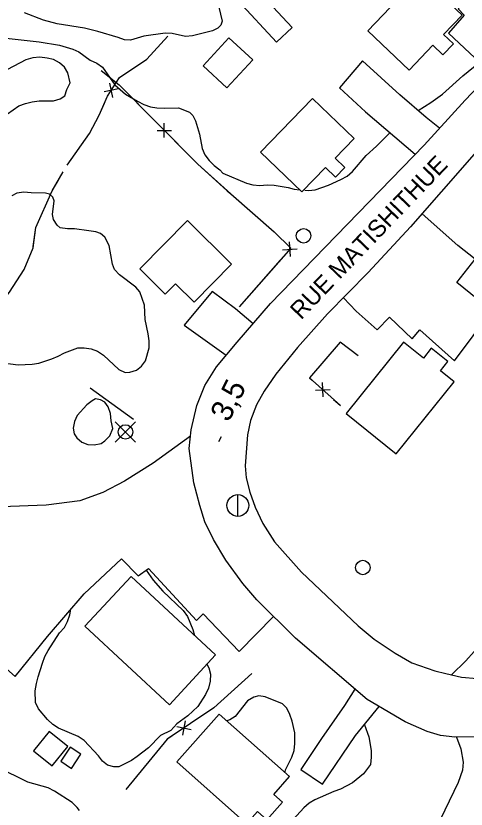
# Model space of a CAD drawing. Extents: x 282461 to 284471, y 5554090 to 5557646.
# Drawn here: x 282851.1 to 282913.1, y 5554638 to 5554747.1 of the extents above; entities that cross this region are included whole.
import ezdxf

# ---------------------------------------------------------------- set-up
doc = ezdxf.new("R2010")
doc.units = 0
for name, color, linetype in [('Niveau 1', 7, 'Continuous'), ('Niveau 15', 7, 'Continuous'), ('Niveau 19', 7, 'Continuous'), ('Niveau 2', 7, 'Continuous'), ('Niveau 21', 7, 'Continuous'), ('Niveau 3', 7, 'Continuous'), ('Niveau 31', 7, 'Continuous'), ('Niveau 36', 7, 'Continuous'), ('Niveau 37', 7, 'Continuous')]:
    doc.layers.add(name, color=color, linetype=linetype)

msp = doc.modelspace()

# ---------------------------------------------------------------- linework, layer by layer
at = {"layer": 'Niveau 1'}
msp.add_lwpolyline([(282879.04, 5554748.29), (282879.48, 5554746.39), (282879.32, 5554745.81), (282878.92, 5554745.4), (282878.17, 5554745.04), (282875.41, 5554744.36), (282874.43, 5554744.28), (282872.63, 5554744.66), (282871.65, 5554744.7), (282868.71, 5554744.31), (282866.86, 5554743.76), (282866.05, 5554743.8), (282865.18, 5554744.13), (282862.39, 5554744.96), (282860.54, 5554745.39), (282856.77, 5554746.02), (282854.91, 5554746.52), (282852.29, 5554747.51)], dxfattribs=at)
at = {"layer": 'Niveau 19'}
for points in [[(282924.29, 5554747.53), (282921.44, 5554750.01), (282917.21, 5554753.94), (282911.98, 5554748.06), (282912.8, 5554747.21), (282910.65, 5554744.74), (282916.5, 5554739.24)], [(282909.42, 5554731.66), (282907.58, 5554733.1), (282903.97, 5554736.23), (282898.8, 5554740.9), (282895.63, 5554737.2), (282899.21, 5554733.9), (282906.05, 5554728.06)], [(282896.18, 5554708.33), (282897.94, 5554706.48), (282900.82, 5554703.92), (282902.52, 5554705.63), (282905.64, 5554702.67), (282906.69, 5554703.89), (282911.48, 5554699.62), (282916.63, 5554706.54), (282911.82, 5554710.4), (282914.34, 5554713.63), (282911.94, 5554715.5), (282907.03, 5554719.86)], [(282883.75, 5554704.75), (282881.35, 5554706.79), (282878.11, 5554709.18), (282874.25, 5554704.54), (282880.04, 5554700.41)], [(282875.13, 5554689.3), (282869.99, 5554685.58), (282866.06, 5554683.08), (282863.08, 5554681.53), (282859.91, 5554680.38), (282855.29, 5554679.79), (282849.14, 5554679.58), (282846.25, 5554679.36), (282844.07, 5554678.4), (282841.34, 5554675.87), (282835.83, 5554669.47), (282842.76, 5554663.5), (282851, 5554656.21), (282855.44, 5554661.71), (282860.5, 5554667.58), (282865.62, 5554672.41), (282867.92, 5554670.07), (282869.35, 5554671.08), (282875.95, 5554663.94), (282876.9, 5554664.84), (282881.84, 5554659.64), (282886.57, 5554664.48)], [(282940.21, 5554676.32), (282938.2, 5554677.94), (282931.93, 5554682.59), (282927.42, 5554676.8), (282928.53, 5554675.9), (282924.96, 5554671.55), (282921.6, 5554668.25), (282919.51, 5554667.11), (282917.59, 5554664.47), (282915.33, 5554660.96), (282913.06, 5554658.38), (282911.05, 5554656.44)], [(282897.78, 5554654.47), (282896.35, 5554652.22), (282893.15, 5554647.7), (282890.33, 5554643.43), (282893.32, 5554641.39), (282897.87, 5554648.08), (282901.09, 5554652.08)], [(282911.75, 5554647.87), (282912.34, 5554646.26), (282912.66, 5554644.41), (282912.57, 5554643.31), (282911.96, 5554641.62), (282902.15, 5554621.29), (282906.75, 5554619.05), (282912.5, 5554631.46), (282916.11, 5554639.08), (282916.56, 5554639.79), (282922.87, 5554633.89), (282925.53, 5554637.57), (282921.56, 5554641.23), (282918.83, 5554644.09), (282922.48, 5554649.58)]]:
    msp.add_lwpolyline(points, dxfattribs=at)
at = {"layer": 'Niveau 2'}
for points in [[(282849.36, 5554744.1), (282854.29, 5554743.55), (282857.13, 5554743.07), (282858.93, 5554742.52), (282859.75, 5554742.13), (282861.33, 5554741), (282862.26, 5554740.61), (282863.02, 5554740.04), (282864.74, 5554737.63), (282865.44, 5554736.95), (282866.21, 5554736.33), (282867.84, 5554735.37)], [(282858.12, 5554736.99), (282858.57, 5554737.87), (282858.26, 5554739.25), (282857.78, 5554740.06), (282857.13, 5554740.63), (282856.26, 5554741.08), (282855.39, 5554741.3), (282854.4, 5554741.4), (282853.42, 5554741.32), (282852.49, 5554741.07), (282849.97, 5554739.7)], [(282906.48, 5554734.06), (282908.23, 5554735.2), (282909.83, 5554736.33), (282912.62, 5554738.86), (282914.11, 5554740.04), (282914.98, 5554740.67)], [(282849.96, 5554733.62), (282851.5, 5554734.74), (282852.42, 5554735.05), (282853.34, 5554735.29), (282854.33, 5554735.43), (282856.29, 5554735.4), (282857.22, 5554735.7), (282857.84, 5554736.12), (282858.12, 5554736.99)], [(282867.84, 5554735.37), (282868.72, 5554734.92), (282869.65, 5554734.59), (282870.52, 5554734.43), (282871.5, 5554734.38), (282873.47, 5554734.47), (282874.98, 5554733.86), (282875.45, 5554733.4), (282875.81, 5554732.66), (282876.36, 5554730.81), (282876.74, 5554728.85), (282877.11, 5554727.99), (282877.7, 5554727.19), (282878.4, 5554726.5), (282879.16, 5554725.94), (282879.58, 5554725.48), (282882.84, 5554724.09), (282883.71, 5554723.87), (282884.7, 5554723.77), (282885.68, 5554723.84), (282886.66, 5554723.8), (282888.58, 5554723.48), (282889.39, 5554723.26), (282890.17, 5554723.18)], [(282890.88, 5554723.11), (282891.36, 5554723.06), (282892.28, 5554723.19), (282894.13, 5554723.8), (282895.85, 5554724.58), (282896.71, 5554725.06), (282897.45, 5554725.71), (282899.32, 5554727.88), (282900.75, 5554729.18), (282902.58, 5554731.03)], [(282863.95, 5554715.5), (282863.35, 5554716.65), (282862.77, 5554717.17), (282862.13, 5554717.39), (282861.14, 5554717.54), (282859.17, 5554717.8), (282858.19, 5554717.79), (282857.2, 5554717.94), (282856.79, 5554718.29), (282856.26, 5554719.09), (282856.13, 5554719.78), (282856.39, 5554721.64), (282856.21, 5554722.16), (282855.74, 5554722.55), (282855.16, 5554722.72), (282853.19, 5554722.74), (282852.2, 5554722.84), (282851.22, 5554722.71), (282850.53, 5554722.35)], [(282845.71, 5554699.82), (282851.44, 5554699.1), (282853.35, 5554699.18), (282854.27, 5554699.32), (282856.06, 5554699.92), (282856.92, 5554700.28), (282857.78, 5554700.76), (282859.62, 5554701.43), (282860.49, 5554701.44), (282861.47, 5554701.28), (282862.34, 5554700.95), (282863.16, 5554700.44), (282865.28, 5554698.45), (282866.15, 5554698.06), (282866.79, 5554698.07), (282867.71, 5554698.37), (282868.39, 5554698.9), (282868.96, 5554699.66), (282869.45, 5554701.41), (282869.43, 5554702.39), (282869.3, 5554703.37), (282868.92, 5554705.34), (282868.83, 5554707.3), (282868.17, 5554709.15), (282867.63, 5554709.77), (282865.35, 5554711.47), (282864.7, 5554712.22), (282864.4, 5554712.96), (282863.95, 5554715.5)], [(282864.24, 5554691.37), (282864.11, 5554692.41), (282863.8, 5554693.33), (282863.33, 5554693.96), (282862.74, 5554694.3), (282862.05, 5554694.4), (282861.59, 5554694.16), (282860.85, 5554693.57), (282859.54, 5554692.1), (282859.15, 5554691.29), (282858.99, 5554690.36), (282859.12, 5554689.61), (282859.48, 5554689.04), (282860.18, 5554688.47), (282861, 5554688.13), (282861.87, 5554688.09), (282862.85, 5554688.28), (282863.36, 5554688.63), (282864.04, 5554689.34), (282864.43, 5554690.33), (282864.24, 5554691.37)], [(282869.02, 5554670.85), (282870.01, 5554669.45), (282871.31, 5554667.97), (282874.14, 5554665.29), (282874.73, 5554664.49), (282875.45, 5554662.7), (282875.7, 5554661.87)], [(282871.01, 5554648.09), (282869.36, 5554646.39), (282867.82, 5554645.21), (282867.01, 5554644.67), (282865.29, 5554643.78), (282864.6, 5554643.77), (282863.73, 5554644.04), (282863.02, 5554644.55), (282862.49, 5554645.3), (282860.49, 5554647.41), (282859.67, 5554647.97), (282856.98, 5554649.09), (282856.17, 5554649.6), (282855.46, 5554650.28), (282854.22, 5554651.77), (282853.8, 5554652.63), (282853.77, 5554654.25), (282853.93, 5554655.24), (282854.15, 5554656.17), (282854.75, 5554658.03), (282855.08, 5554658.97), (282855.53, 5554659.78), (282857.11, 5554662.24), (282857.79, 5554662.95), (282858.19, 5554663.76), (282858.52, 5554664.7), (282858.68, 5554665.47)], [(282877.4, 5554657.9), (282877.68, 5554657.41), (282877.87, 5554656.54), (282877.83, 5554655.56), (282877.61, 5554654.63), (282877.22, 5554653.75), (282876.15, 5554652.11), (282874.78, 5554650.82), (282873.24, 5554649.69), (282872.44, 5554648.81), (282871.01, 5554648.09)], [(282889.11, 5554650.08), (282888.8, 5554651), (282888.38, 5554651.87), (282887.79, 5554652.44), (282885.41, 5554653.44), (282884.54, 5554653.54), (282883.85, 5554653.36), (282882.99, 5554652.88), (282881.29, 5554650.71), (282880.54, 5554650.24), (282880.13, 5554650.14)], [(282888.15, 5554643.12), (282888.23, 5554643.36), (282889.07, 5554645.11), (282889.4, 5554646.04), (282889.5, 5554647.02), (282889.48, 5554648.47), (282889.11, 5554650.08)], [(282899.09, 5554649.58), (282899.67, 5554647.93), (282899.99, 5554646.03), (282900.01, 5554645.1)], [(282900.01, 5554645.1), (282899.91, 5554644.12), (282898.94, 5554642.83), (282897.46, 5554641.59), (282895.8, 5554640.7), (282894.88, 5554640.39), (282892.24, 5554639.25), (282891.49, 5554638.78), (282890.75, 5554638.13), (282888.76, 5554636.01)], [(282859.84, 5554637.78), (282859.54, 5554638.18), (282858.83, 5554638.87), (282856.43, 5554640.45), (282855.56, 5554640.9), (282852.77, 5554641.67), (282848.51, 5554643.74)]]:
    msp.add_lwpolyline(points, dxfattribs=at)
at = {"layer": 'Niveau 21'}
for points in [[(282878.3, 5554675.07), (282877.1, 5554677.48), (282876.42, 5554679.73), (282875.62, 5554682.84), (282874.96, 5554687.58), (282875.21, 5554690.13), (282876.02, 5554693.51), (282877.13, 5554696.24), (282878.71, 5554698.82), (282881.55, 5554702.22), (282886.15, 5554707.51), (282907.28, 5554729.33), (282912.94, 5554735.51), (282919.4, 5554742.27), (282923.97, 5554747.21), (282929.38, 5554752.63), (282934.38, 5554758.26), (282952.63, 5554779.99), (282962.67, 5554792.32), (282966.75, 5554797.77), (282970.24, 5554803.68), (282971.64, 5554808.46), (282972.65, 5554813.8), (282973.48, 5554823.09)], [(282918.39, 5554732.87), (282905.44, 5554718.07), (282899.59, 5554711.78), (282894.01, 5554706.13), (282889.86, 5554701.49), (282886.88, 5554697.79), (282885.3, 5554695.45), (282884.23, 5554693.58), (282883.4, 5554691.42), (282882.97, 5554689.45), (282882.66, 5554685.21), (282882.81, 5554683.53), (282883.3, 5554681.57), (282884.03, 5554679.49), (282885.11, 5554677.25), (282886.71, 5554674.73), (282890.4, 5554670.57), (282898.2, 5554663.17), (282900.42, 5554661.36), (282903.32, 5554659.44), (282905.6, 5554658.09), (282908.77, 5554656.99), (282910.29, 5554656.61), (282912.43, 5554656.12), (282914.58, 5554655.93)], [(282977.15, 5554709.01), (282965.42, 5554696.55), (282958.45, 5554688.63), (282945.11, 5554673.19), (282939.64, 5554666.16), (282933.59, 5554659.25), (282926.34, 5554651.73), (282922.75, 5554649.66), (282918.67, 5554648.38), (282915.9, 5554647.93), (282911.51, 5554647.87), (282909.54, 5554648.12), (282907.73, 5554648.67), (282904.67, 5554650), (282899.45, 5554653.04), (282889.58, 5554661.49), (282884.25, 5554666.78), (282882.33, 5554668.99), (282880.02, 5554672.2), (282878.3, 5554675.07)]]:
    msp.add_lwpolyline(points, dxfattribs=at)
at = {"layer": 'Niveau 3'}
msp.add_line((282879.06, 5554688.53), (282879.42, 5554689.25), dxfattribs=at)
at = {"layer": 'Niveau 31'}
for points in [[(282912.51, 5554747.2), (282906.81, 5554752.65), (282899.55, 5554745.06), (282905.23, 5554739.62), (282908.51, 5554743.05), (282909.87, 5554741.76), (282911.32, 5554743.27), (282909.98, 5554744.55), (282912.51, 5554747.2)], [(282889.13, 5554745.51), (282883.87, 5554751.17), (282881.71, 5554749.17), (282886.97, 5554743.5), (282889.13, 5554745.51)], [(282883.71, 5554741.03), (282880.43, 5554744.07), (282876.86, 5554740.23), (282880.14, 5554737.19), (282883.71, 5554741.03)], [(282891.91, 5554735.73), (282884.79, 5554728.34), (282890.47, 5554722.87), (282893.73, 5554726.26), (282895.12, 5554724.91), (282896.4, 5554726.24), (282895.07, 5554727.53), (282897.65, 5554730.21), (282891.91, 5554735.73)], [(282880.79, 5554712.94), (282874.74, 5554718.93), (282868.16, 5554712.28), (282871.65, 5554708.83), (282873.06, 5554710.25), (282875.63, 5554707.72), (282880.79, 5554712.94)], [(282896.56, 5554692.42), (282903.46, 5554686.86), (282911.42, 5554696.76), (282909.53, 5554698.28), (282910.56, 5554699.55), (282908.28, 5554701.39), (282907.19, 5554700.03), (282904.45, 5554702.23), (282896.56, 5554692.42)], [(282878.6, 5554659.2), (282866.96, 5554669.99), (282860.61, 5554663.14), (282872.25, 5554652.34), (282878.6, 5554659.2)], [(282888.78, 5554642.44), (282879.09, 5554651.04), (282873.25, 5554644.46), (282882.85, 5554635.93), (282884.38, 5554637.65), (282885.66, 5554636.51), (282887.8, 5554638.93), (282886.61, 5554639.99), (282888.78, 5554642.44)], [(282858.24, 5554646.57), (282855.69, 5554648.64), (282853.54, 5554646.01), (282856.08, 5554643.93), (282858.24, 5554646.57)], [(282860.06, 5554645.54), (282858.59, 5554646.51), (282857.29, 5554644.56), (282858.77, 5554643.58), (282860.06, 5554645.54)]]:
    msp.add_lwpolyline(points, dxfattribs=at)
at = {"layer": 'Niveau 36'}
for p, q in [((282867.59, 5554688.44), (282864.77, 5554691.26)), ((282864.77, 5554688.44), (282867.59, 5554691.26)), ((282881.65, 5554678.25), (282881.65, 5554681.25))]:
    msp.add_line(p, q, dxfattribs=at)
for centre, radius in [((282890.7, 5554716.84), 1), ((282866.19, 5554689.86), 1), ((282881.66, 5554679.75), 1.5), ((282898.86, 5554671.21), 1)]:
    msp.add_circle(centre, radius, dxfattribs=at)
at = {"layer": 'Niveau 37'}
for p, q in [((282865.21, 5554737.08), (282863.26, 5554736.65)), ((282864.45, 5554735.89), (282864.02, 5554737.84)), ((282871.53, 5554730.35), (282871.53, 5554732.35)), ((282870.53, 5554731.35), (282872.53, 5554731.35)), ((282887.8, 5554714.93), (282889.8, 5554715.06)), ((282888.73, 5554716), (282888.86, 5554714)), ((282893.41, 5554694.67), (282893.3, 5554696.67)), ((282892.35, 5554695.61), (282894.35, 5554695.72)), ((282874.42, 5554650.11), (282874.04, 5554648.15)), ((282873.25, 5554649.32), (282875.21, 5554648.94))]:
    msp.add_line(p, q, dxfattribs=at)
for points in [[(282858.14, 5554726.58), (282861.25, 5554730.92), (282862.57, 5554733.43), (282863.72, 5554736.06), (282865.36, 5554738.63), (282869.13, 5554741.13), (282872.01, 5554744.3)], [(282865.31, 5554738.55), (282865.36, 5554738.63), (282869.13, 5554741.13), (282872.01, 5554744.3)], [(282862.82, 5554739.58), (282865.32, 5554737.59), (282876.15, 5554726.71), (282880.67, 5554722.61), (282886.65, 5554717.39), (282888.94, 5554715.16), (282881.85, 5554707.07)], [(282862.82, 5554739.58), (282865.32, 5554737.59), (282870.12, 5554732.77)], [(282858.14, 5554726.58), (282861.25, 5554730.92), (282862.57, 5554733.43), (282863.3, 5554735.1)], [(282872.94, 5554729.93), (282876.15, 5554726.71), (282880.19, 5554723.05)], [(282830.2, 5554676.25), (282829.95, 5554680.47), (282830.24, 5554684.17), (282830.82, 5554687.63), (282831.54, 5554690.24), (282835.62, 5554695.22), (282838.02, 5554698.32), (282840.56, 5554700.56), (282843.04, 5554702.24), (282847.81, 5554706.08), (282850.22, 5554709.07), (282852.25, 5554712.23), (282853.47, 5554715.2), (282853.83, 5554717.98), (282856.1, 5554723.04), (282857.63, 5554725.65)], [(282853.49, 5554715.37), (282853.83, 5554717.98), (282856.1, 5554723.04), (282857.02, 5554724.61)], [(282880.19, 5554723.05), (282880.67, 5554722.61), (282886.65, 5554717.39), (282887.66, 5554716.4)], [(282848.43, 5554706.84), (282850.22, 5554709.07), (282852.25, 5554712.23), (282853.47, 5554715.2), (282853.49, 5554715.37)], [(282887.48, 5554713.49), (282881.85, 5554707.07)], [(282898.2, 5554700.35), (282895.74, 5554702.22), (282891.54, 5554697.3), (282895.77, 5554693.49)], [(282898.2, 5554700.35), (282895.74, 5554702.22), (282891.54, 5554697.3), (282891.87, 5554697)], [(282861.34, 5554695.92), (282867.31, 5554691.61)], [(282861.34, 5554695.92), (282867.31, 5554691.61)], [(282894.84, 5554694.33), (282895.77, 5554693.49)], [(282883.58, 5554656.61), (282878.34, 5554651.91), (282871.94, 5554647.58), (282866.25, 5554640.68)], [(282883.58, 5554656.61), (282878.34, 5554651.91), (282875.89, 5554650.25)], [(282872.57, 5554648.01), (282871.94, 5554647.58), (282866.25, 5554640.68)]]:
    msp.add_lwpolyline(points, dxfattribs=at)

# ---------------------------------------------------------------- texts
at = {"layer": 'Niveau 15'}
msp.add_text('RUE MATISHITHUE', height=2.4, rotation=46.2707, dxfattribs=at).set_placement((282890.35, 5554705.2))
at = {"layer": 'Niveau 3'}
msp.add_text('3,5  ', height=3, rotation=63.2825, dxfattribs=at).set_placement((282880.39, 5554691.09))

doc.saveas('drawing.dxf')
